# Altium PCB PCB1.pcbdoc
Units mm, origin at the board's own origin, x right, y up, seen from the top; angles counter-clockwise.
Board outline 211.69 x 110.15 mm, 2 copper layers (Top Layer, Bottom Layer); 2 components, 5 nets, 18 pads, 19 vias.
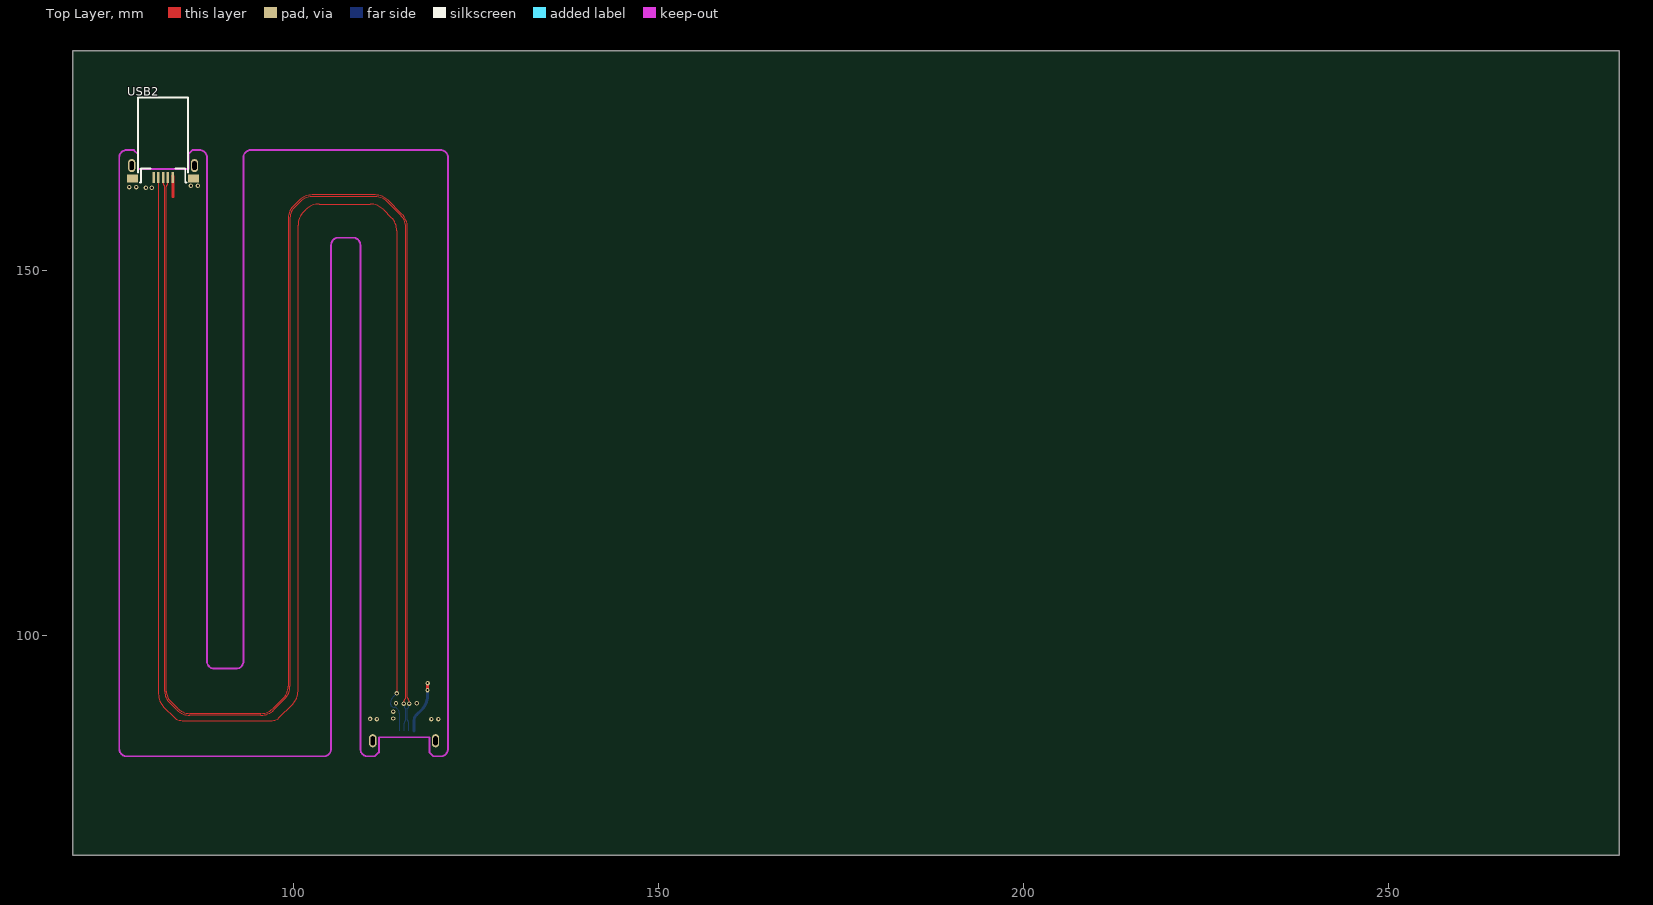
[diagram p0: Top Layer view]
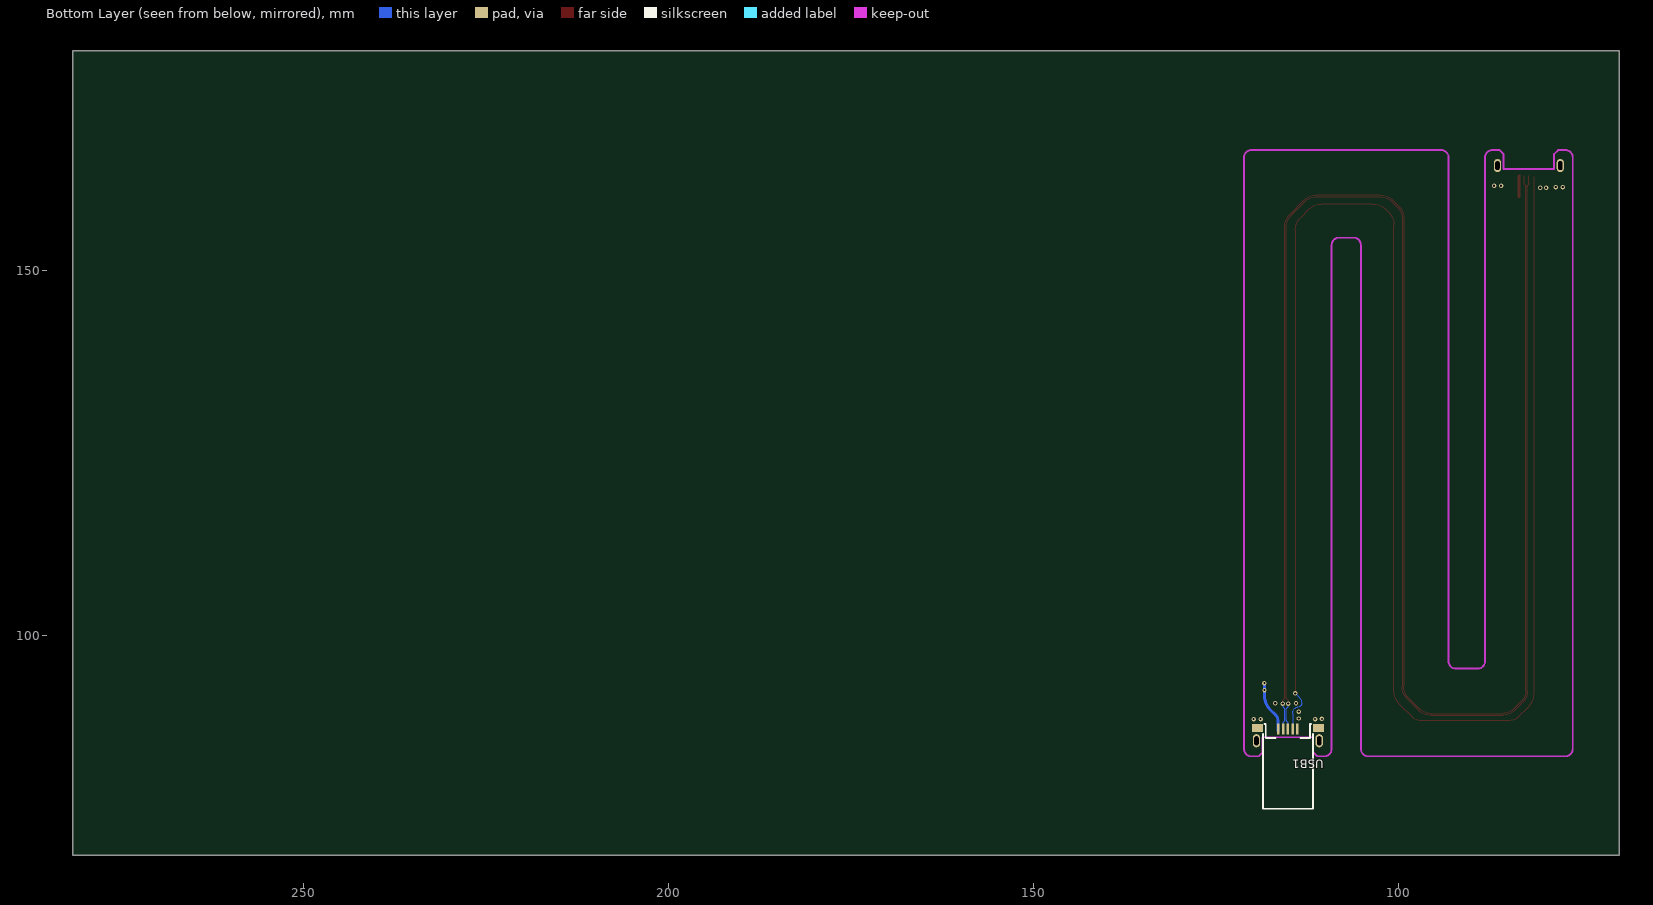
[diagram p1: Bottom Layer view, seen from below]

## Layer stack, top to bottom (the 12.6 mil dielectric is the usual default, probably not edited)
Top Layer: signal copper (thickness not stored)
Dielectric: dielectric 0.32, FR-4, Dk 4.8
Bottom Layer: signal copper (thickness not stored)

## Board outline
281.54,69.85 69.85,69.85 69.85,180.004 281.54,180.004

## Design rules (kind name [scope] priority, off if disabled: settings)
Clearance copperThickness1oz [All] p1: gap=0.178 ignorepadtopadclearanceinfootprint=FALSE except(0.102: Track-Track; 0.152: Track-SMDPad SMDPad-SMDPad Track-THPad SMDPad-THPad THPad-THPad Track-Via SMDPad-Via THPad-Via Via-Via SMDPad-Fill THPad-Fill Via-Fill Fill-Fill Track-Region SMDPad-Region THPad-Region Via-Region Region-Region Track-Poly SMDPad-Poly THPad-Poly Via-Poly Fill-Poly Region-Poly Poly-Poly Track-Text SMDPad-Text THPad-Text Via-Text Fill-Text Region-Text Poly-Text Text-Text; 0.175: Track-Hole SMDPad-Hole THPad-Hole Via-Hole Fill-Hole Region-Hole Poly-Hole Text-Hole Sheet-Hole; 0.3: Track-Fill Fill-Region Track-Sheet SMDPad-Sheet THPad-Sheet Via-Sheet Fill-Sheet Region-Sheet Poly-Sheet Text-Sheet)
Clearance copperThickness2oz [All] p1: gap=0.178 ignorepadtopadclearanceinfootprint=FALSE except(0.152: Track-SMDPad SMDPad-SMDPad Track-THPad SMDPad-THPad THPad-THPad Track-Via SMDPad-Via THPad-Via Via-Via SMDPad-Fill THPad-Fill Via-Fill Fill-Fill Track-Region SMDPad-Region THPad-Region Via-Region Region-Region Track-Poly SMDPad-Poly THPad-Poly Via-Poly Fill-Poly Region-Poly Poly-Poly Track-Text SMDPad-Text THPad-Text Via-Text Fill-Text Region-Text Poly-Text Text-Text; 0.175: Track-Hole SMDPad-Hole THPad-Hole Via-Hole Fill-Hole Region-Hole Poly-Hole Text-Hole Sheet-Hole; 0.203: Track-Track; 0.3: Track-Fill Fill-Region Track-Sheet SMDPad-Sheet THPad-Sheet Via-Sheet Fill-Sheet Region-Sheet Poly-Sheet Text-Sheet)
DiffPairsRouting differentialPair [All] p1: maxuncoupledlength=10 maxlimit=3.937 mostfreqgap=3.937 toplayer_minwidth=5 toplayer_prefwidth=10 toplayer_maxwidth=100 bottomlayer_minwidth=5 bottomlayer_prefwidth=10 bottomlayer_maxwidth=100
DiffPairsRouting USB2_0 [All] p1: maxuncoupledlength=10 maxlimit=3.937 mostfreqgap=3.937 toplayer_minwidth=5.315 toplayer_prefwidth=5.315 toplayer_maxwidth=5.315 bottomlayer_minwidth=5.315 bottomlayer_prefwidth=5.315 bottomlayer_maxwidth=5.315
PasteMaskExpansion pasteMaskExpansion [All] p1:
PlaneConnect innerPlane [All] p1: planeconnectstyle=Relief reliefexpansion=0.508 reliefentries=4 reliefconductorwidth=0.254 reliefairgap=0.254
PolygonConnect copperRegion [All] p1: connectstyle=Relief reliefentries=4 reliefconductorwidth=10 polygonreliefangle="90 Angle" airgapwidth=10
PolygonConnect copperRegion1 [All] p1: connectstyle=Direct reliefentries=4 reliefconductorwidth=10 polygonreliefangle="90 Angle" airgapwidth=10
PolygonConnect VCC [All] p1: connectstyle=Direct reliefentries=4 reliefconductorwidth=10 polygonreliefangle="90 Angle" airgapwidth=10
RoutingVias viaSize [All] p1: viastyle="Through Hole" holewidth=12.0078 minholewidth=11.811 maxholewidth=248.0314 width=24.0158 minwidth=19.685 maxwidth=393.7008
SolderMaskExpansion solderMaskExpansion [All] p1: useseparateexpansions=TRUE expansion=2.0079 expansionbottom=2.0079
Width copperThickness1oz [All] p1: maxlimit=100 minlimit=5 preferedwidth=10
Width copperThickness2oz [All] p1: maxlimit=100 minlimit=8 preferedwidth=10

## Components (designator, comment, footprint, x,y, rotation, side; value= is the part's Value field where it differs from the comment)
USB1 "MICRO-ZD-103PWB" MICRO-USB-SMD_ZD-103PWB 115.201,86.427 r0 bottom
USB2 "MICRO-ZD-103PWB" MICRO-USB-SMD_ZD-103PWB 82.201,163.427 r0 top locked

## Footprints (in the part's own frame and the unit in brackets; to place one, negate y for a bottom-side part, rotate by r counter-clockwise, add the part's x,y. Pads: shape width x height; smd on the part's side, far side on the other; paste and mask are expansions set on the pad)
MICRO-USB-SMD_ZD-103PWB [mm]
  rect 0.35x1.5 smd: 1(1.3,-0.725) 2(0.65,-0.725) 3(0,-0.725) 4(-0.65,-0.725) 5(-1.3,-0.725)
  oval 1x1.8 hole 0.6 slot 1.2 at 90 deg: 6(-4.3,0.875) 6(4.3,0.875)
  rect 1.5x1.1 smd: 7(-4.175,-0.875) 7(4.175,-0.875)
  Board Outline Layer lines w0.254: -3.43,0.4 -3.43,2.385 -3.43,0.4 ; -3.43,0.4 3.47,0.4 ; -3.43,0.4 3.47,0.4 ; 3.47,0.4 3.47,2.4 3.47,0.4
  silkscreen extent -3.43,-1.43 3.42,10.18

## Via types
v1: diameter 0.61, hole 0.305, Top Layer to Bottom Layer, 19 vias

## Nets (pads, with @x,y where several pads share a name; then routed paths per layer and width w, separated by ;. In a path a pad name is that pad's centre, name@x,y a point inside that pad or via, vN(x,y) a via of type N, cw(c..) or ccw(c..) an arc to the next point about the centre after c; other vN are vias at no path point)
D+: 
D-: USB1.2 USB2.2 | length 244.2
  Top Layer w0.135: USB2.2@82.851,162.902 82.851,161.914 cw(c82.497,161.914) 82.748,161.663 ccw(c82.998,161.413) 82.644,161.413 82.644,92.319 ccw(c84.487,92.319) 83.184,91.015 84.251,89.948 ccw(c85.881,91.578) 85.881,89.273 95.572,89.273 ccw(c95.572,91.578) 97.202,89.948 98.651,91.398 ccw(c97.022,93.028) 99.327,93.028 99.327,157.158 cw(c101.485,157.158) 99.959,158.684 100.808,159.533 cw(c102.604,157.737) 102.604,160.277 111.225,160.277 cw(c111.225,157.737) 113.021,159.533 114.9,157.654 cw(c113.104,155.858) 115.644,155.858 115.644,91.542 ccw(c116.094,91.542) 115.776,91.224 cw(c115.458,90.906) 115.907,90.906 v1(115.907,90.652)
  Bottom Layer w0.135: USB1.2@115.851,86.952 115.851,87.94 ccw(c115.497,87.94) 115.748,88.191 cw(c115.998,88.441) 115.644,88.441 115.644,89.948 ccw(c115.008,90.584) 115.907,90.584 v1(115.907,90.652)
GND: USB1.5 USB1.6 USB1.7 USB2.5 USB2.6 USB2.7
  other v1: 111.478,88.529 118.942,88.53 119.889,88.521 110.531,88.539 113.705,88.604 113.715,89.551 114.083,90.69 116.921,90.697 79.845,161.275 80.646,161.255 78.527,161.353 77.58,161.362 86.011,161.545 86.959,161.536
ID: USB1.4 USB2.4 | length 244.2
  Top Layer w0.135: USB2.4@81.561,162.764 81.561,91.967 ccw(c84.101,91.967) 82.305,90.171 83.694,88.781 ccw(c84.808,89.895) 84.808,88.32 97.162,88.32 ccw(c97.162,89.593) 98.062,88.693 99.934,90.564 ccw(c98.138,92.36) 100.678,92.36 100.678,156.155 cw(c103.218,156.155) 101.422,157.951 101.77,158.299 cw(c103.566,156.503) 103.566,159.043 110.543,159.043 cw(c110.543,156.503) 112.339,158.299 113.458,157.18 cw(c111.662,155.384) 114.202,155.384 v1(114.202,92.033)
  Bottom Layer w0.135: v1(114.202,92.033) 113.652,91.483 ccw(c114.43,90.705) 113.33,90.705 113.33,90.584 ccw(c113.697,90.584) 113.437,90.324 ccw(c113.842,90.729) 113.842,90.156 113.88,90.156 cw(c113.88,89.73) 114.181,90.032 114.308,89.905 cw(c113.711,89.308) 114.556,89.308 USB1.4@114.556,86.957
VCC: USB1.1 USB2.1 | length 11
  Top Layer w0.4: USB2.1@83.512,162.896 83.54,162.868 83.54,160.035 ; v1(118.399,92.502) 118.405,92.508 v1(118.405,93.458)
  Bottom Layer w0.4: USB1.1@116.537,86.87 116.537,88.217 cw(c117.804,88.217) 116.908,89.113 117.648,89.853 ccw(c115.852,91.649) 118.392,91.649 118.399,91.655 v1(118.399,92.502) 118.405,92.508 v1(118.405,93.458)
pads on no net: USB1.3 USB2.3
copper on no net: | length 244.2
  Top Layer w0.135: 82.201,162.902 82.201,161.914 ccw(c82.556,161.914) 82.305,161.663 cw(c82.055,161.413) 82.409,161.413 82.409,92.319 ccw(c84.487,92.319) 83.018,90.849 84.085,89.782 ccw(c85.881,91.578) 85.881,89.038 95.572,89.038 ccw(c95.572,91.578) 97.368,89.782 98.818,91.232 ccw(c97.022,93.028) 99.562,93.028 99.562,157.158 cw(c101.485,157.158) 100.125,158.518 100.974,159.367 cw(c102.604,157.737) 102.604,160.042 111.225,160.042 cw(c111.225,157.737) 112.855,159.367 114.734,157.488 cw(c113.104,155.858) 115.409,155.858 115.409,91.542 cw(c114.959,91.542) 115.277,91.224 ccw(c115.595,90.906) 115.145,90.906 v1(115.145,90.652)
  Bottom Layer w0.135: v1(115.145,90.652) 115.145,90.584 ccw(c116.045,90.584) 115.409,89.948 115.409,88.441 cw(c115.055,88.441) 115.305,88.191 ccw(c115.556,87.94) 115.201,87.94 115.201,86.952

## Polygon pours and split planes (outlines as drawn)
GND on Top Layer (solid, remove dead copper): 76.201,160.778 88.201,160.778 88.201,166.427 76.201,166.427
GND on Bottom Layer (solid, remove dead copper, pour order 6): 76.201,83.142 121.124,83.142 121.124,166.427 76.201,166.427
GND on Top Layer (solid, remove dead copper, pour order 2): 109.201,83.427 121.201,83.427 121.201,91.427 109.201,91.427
VCC on Top Layer (solid, remove dead copper, pour order 4): 76.223,88.301 121.222,88.301 121.222,166.471 76.223,166.471

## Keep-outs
Board Outline Layer:
  lines w0.254: 76.201,84.427 76.2,165.426 cw(c77.2,165.426) 77.203,166.426 78.201,166.427 78.739,165.889 cw(c78.663,165.812) 78.771,165.812 ; 76.201,84.43 ccw(c77.201,84.427) 77.201,83.427 104.201,83.427 ; 85.671,165.827 cw(c85.84,165.827) 85.721,165.946 86.201,166.427 87.201,166.427 cw(c87.201,165.427) 88.201,165.424 88.201,96.43 ccw(c89.201,96.427) 89.201,95.427 92.201,95.427 ; 92.199,95.427 ccw(c92.201,96.427) 93.201,96.427 93.201,165.427 cw(c94.201,165.427) 94.204,166.427 101.201,166.427 120.201,166.427 cw(c120.201,165.427) 121.201,165.424 ; 104.199,83.427 ccw(c104.201,84.427) 105.201,84.427 105.201,153.427 cw(c106.201,153.427) 106.204,154.427 108.201,154.427 cw(c108.201,153.427) 109.201,153.424 ; 109.201,84.427 109.201,153.427 ; 109.201,84.43 ccw(c110.201,84.427) 110.201,83.427 111.201,83.427 111.739,83.965 ccw(c111.663,84.042) 111.771,84.042 ; 118.671,84.027 ccw(c118.84,84.027) 118.721,83.907 119.201,83.427 120.199,83.427 ccw(c120.201,84.427) 121.201,84.427 121.201,165.427

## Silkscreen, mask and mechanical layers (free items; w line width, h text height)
Mech6:
  lines w0.254: 128.201,94.37 275.19,94.37 ; 128.201,94.624 128.201,152.427 275.19,152.427 275.19,94.624 ; 128.201,100.176 275.19,100.176 ; 128.201,105.981 275.19,105.981 ; 128.201,111.787 275.19,111.787 ; 128.201,117.593 275.19,117.593 ; 128.201,123.398 275.19,123.398 ; 128.201,129.204 275.19,129.204 ; 128.201,135.01 275.19,135.01 ; 128.201,140.816 275.19,140.816 ; 128.201,146.621 275.19,146.621 ; 164.456,94.624 164.456,152.427 ; 192.799,94.624 192.799,152.427 ; 209.054,94.624 209.054,152.427 ; 232.449,94.624 232.449,152.427 ; 252.958,94.624 252.958,152.427
  text "Layer" at 131.104,149.524 h2.03
  text "Type" at 167.359,149.524 h2.03
  text "Material" at 195.702,149.524 h2.03
  text "Thickness(mm)" at 211.957,149.524 h2.03
  text "Permittivity" at 235.352,149.524 h2.03
  text "Loss Tangent" at 255.861,149.524 h2.03
  text "Top Silkscreen Layer" at 131.104,143.718 h2.03
  text "TOP_SILK" at 167.359,143.718 h2.03
  text "0" at 211.957,143.718 h2.03
  text "0" at 235.352,143.718 h2.03
  text "0" at 255.861,143.718 h2.03
  text "Top Paste Mask Layer" at 131.104,137.913 h2.03
  text "TOP_PASTE_MASK" at 167.359,137.913 h2.03
  text "0" at 211.957,137.913 h2.03
  text "0" at 235.352,137.913 h2.03
  text "0" at 255.861,137.913 h2.03
  text "Top Solder Mask Layer" at 131.104,132.107 h2.03
  text "TOP_SOLDER_MASK" at 167.359,132.107 h2.03
  text "0.01" at 211.957,132.107 h2.03
  text "3.3" at 235.352,132.107 h2.03
  text "0.02" at 255.861,132.107 h2.03
  text "Top Layer" at 131.104,126.301 h2.03
  text "TOP" at 167.359,126.301 h2.03
  text "0.012" at 211.957,126.301 h2.03
  text "0" at 235.352,126.301 h2.03
  text "0" at 255.861,126.301 h2.03
  text "Dielectric2" at 131.104,120.496 h2.03
  text "SUBSTRATE" at 167.359,120.496 h2.03
  text "PI" at 195.702,120.496 h2.03
  text "0.066" at 211.957,120.496 h2.03
  text "4.5" at 235.352,120.496 h2.03
  text "0" at 255.861,120.496 h2.03
  text "Bottom Layer" at 131.104,114.69 h2.03
  text "BOTTOM" at 167.359,114.69 h2.03
  text "0.012" at 211.957,114.69 h2.03
  text "0" at 235.352,114.69 h2.03
  text "0" at 255.861,114.69 h2.03
  text "Bottom Solder Mask Layer" at 131.104,108.884 h2.03
  text "BOT_SOLDER_MASK" at 167.359,108.884 h2.03
  text "0.01" at 211.957,108.884 h2.03
  text "3.3" at 235.352,108.884 h2.03
  text "0.02" at 255.861,108.884 h2.03
  text "Bottom Paste Mask Layer" at 131.104,103.078 h2.03
  text "BOT_PASTE_MASK" at 167.359,103.078 h2.03
  text "0" at 211.957,103.078 h2.03
  text "0" at 235.352,103.078 h2.03
  text "0" at 255.861,103.078 h2.03
  text "Bottom Silkscreen Layer" at 131.104,97.273 h2.03
  text "BOT_SILK" at 167.359,97.273 h2.03
  text "0" at 211.957,97.273 h2.03
  text "0" at 235.352,97.273 h2.03
  text "0" at 255.861,97.273 h2.03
